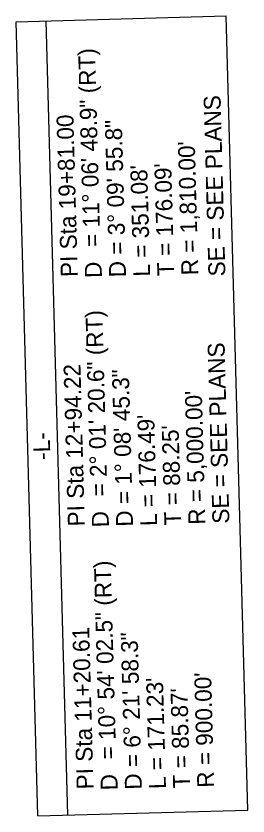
# Model space of a CAD drawing. Extents: x 1835351 to 1836442, y 993887 to 995358.
# Drawn here: x 1835350.9 to 1835447.1, y 994512.7 to 994844.5 of the extents above; entities that cross this region are included whole.
import ezdxf

# ---------------------------------------------------------------- set-up
doc = ezdxf.new("R2010")
doc.units = 0
doc.layers.add('Prop Horizontal Alignment Curve and Spiral Data', color=7, linetype='Continuous')
doc.layers.add('Prop Horizontal Alignment Station Label', color=7, linetype='Continuous')

msp = doc.modelspace()

# ---------------------------------------------------------------- linework, layer by layer
at = {"layer": 'Prop Horizontal Alignment Station Label'}
for p, q in [((1835350.91, 994842.16), (1835438.08, 994844.54)), ((1835447.07, 994515.13), (1835438.08, 994844.54)), ((1835359.9, 994512.75), (1835350.91, 994842.16)), ((1835372.43, 994513.09), (1835363.43, 994842.5)), ((1835359.9, 994512.75), (1835447.07, 994515.13))]:
    msp.add_line(p, q, dxfattribs=at)

# ---------------------------------------------------------------- texts
at = {"layer": 'Prop Horizontal Alignment Curve and Spiral Data'}
for s, p in [('= 11%%d 06\' 48.9" (RT)', (1835385.89, 994748.83)), ('SE = SEE PLANS', (1835437.72, 994736.62)), ('PI Sta 19+81.00', (1835376.52, 994736.39)), ('D = 3%%d 09\' 55.8"', (1835396.53, 994736.27)), ("R = 1,810.00'", (1835426.52, 994737.09)), ("L = 351.08'", (1835406.53, 994736.54)), ("T = 176.09'", (1835416.53, 994736.81)), ('D', (1835386.54, 994735.99)), ('= 2%%d 01\' 20.6" (RT)', (1835388.8, 994645.39)), ('SE = SEE PLANS', (1835439.38, 994634.06)), ('PI Sta 12+94.22', (1835379.44, 994632.95)), ('D = 1%%d 08\' 45.3"', (1835399.45, 994632.82)), ("R = 5,000.00'", (1835429.44, 994633.64)), ("L = 176.49'", (1835409.44, 994633.09)), ("T = 88.25'", (1835419.44, 994633.37)), ('-L-', (1835365.19, 994660.53)), ('D', (1835389.45, 994632.55)), ('= 10%%d 54\' 02.5" (RT)', (1835392.44, 994536.32)), ('PI Sta 11+20.61', (1835383.07, 994523.88)), ('D = 6%%d 21\' 58.3"', (1835403.08, 994523.75)), ("R = 900.00'", (1835433.07, 994524.57)), ("L = 171.23'", (1835413.08, 994524.02)), ("T = 85.87'", (1835423.08, 994524.3)), ('D', (1835393.09, 994523.48))]:
    msp.add_text(s, height=7, rotation=91.5644, dxfattribs=at).set_placement(p)

doc.saveas('drawing.dxf')
